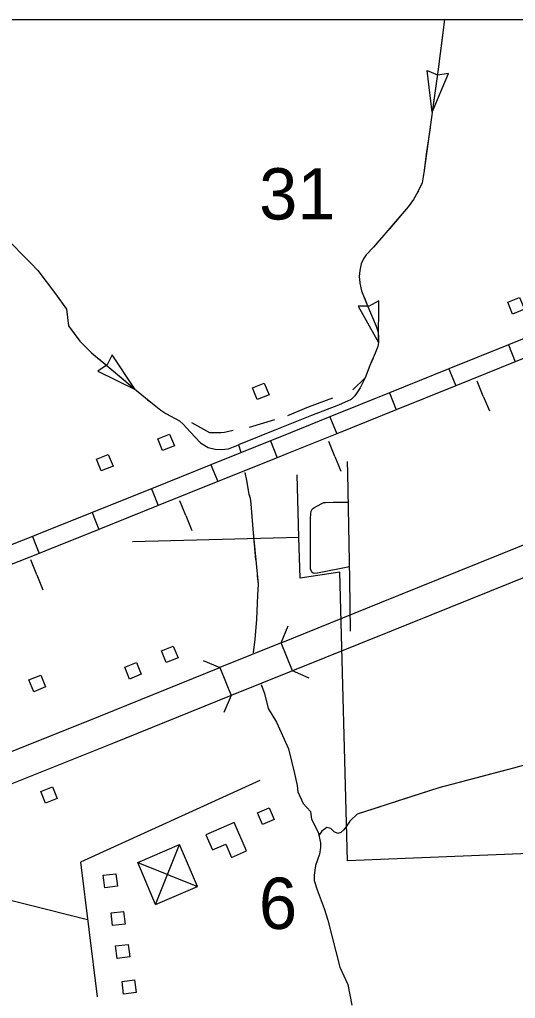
# Model space of a CAD drawing. Extents: x 155 to 3386, y 68 to 2138.
# Drawn here: x 1248.7 to 1365.4, y 1078.7 to 1309 of the extents above; entities that cross this region are included whole.
import ezdxf

# ---------------------------------------------------------------- set-up
doc = ezdxf.new("R2010")
doc.units = 0
for name, color, linetype in [('Default', 7, 'Continuous'), ('E_No Plot', 7, 'Continuous'), ('Level 15', 7, 'Continuous'), ('Level 32', 7, 'Continuous'), ('Level 33', 7, 'Continuous'), ('Level 35', 7, 'Continuous'), ('Level 37', 7, 'Continuous'), ('Level 4', 7, 'Continuous'), ('Level 40', 7, 'Continuous'), ('Level 43', 7, 'Continuous'), ('Level 5', 7, 'Continuous'), ('Level 56', 7, 'Continuous'), ('Level 57', 7, 'Continuous'), ('Level 58', 7, 'Continuous'), ('Level 6', 7, 'Continuous')]:
    doc.layers.add(name, color=color, linetype=linetype)

msp = doc.modelspace()

# ---------------------------------------------------------------- linework, layer by layer
at = {"layer": 'Default'}
msp.add_lwpolyline([(1150.5, 1308.99), (2342.15, 1308.99), (2342.15, 348.58), (1150.5, 348.58)], close=True, dxfattribs=at)
at = {"layer": 'E_No Plot'}
msp.add_lwpolyline([(1150.5, 1308.99), (2342.15, 1308.99), (2342.15, 348.58), (1150.5, 348.58)], close=True, dxfattribs=at)
msp.add_lwpolyline([(1150.5, 1308.99), (2342.15, 1308.99), (2342.15, 348.58), (1150.5, 348.58)], close=True, dxfattribs=at)
at = {"layer": 'Level 15'}
for p, q in [((1312.94, 1155.76), (1310.27, 1162.39)), ((1295.82, 1156.56), (1298.5, 1149.93))]:
    msp.add_line(p, q, dxfattribs=at)
for points in [[(1310.27, 1162.39), (1333.46, 1171.74), (1375.25, 1188.62)], [(1377.92, 1181.99), (1336.14, 1165.12), (1312.94, 1155.76)], [(1310.27, 1162.39), (1295.82, 1156.56)], [(1150.5, 1098.18), (1199.11, 1117.76), (1267.73, 1145.22), (1295.82, 1156.56)], [(1312.94, 1155.76), (1298.5, 1149.93)], [(1298.5, 1149.93), (1270.4, 1138.6), (1201.77, 1111.13), (1150.5, 1090.48)]]:
    msp.add_lwpolyline(points, dxfattribs=at)
at = {"layer": 'Level 32'}
for p, q in [((1363.72, 1232.44), (1365.33, 1228.47)), ((1349.73, 1226.8), (1351.33, 1222.83)), ((1335.74, 1221.16), (1337.34, 1217.19)), ((1321.75, 1215.52), (1323.35, 1211.54)), ((1307.76, 1209.88), (1309.36, 1205.91)), ((1293.76, 1204.25), (1295.36, 1200.28)), ((1279.77, 1198.62), (1281.36, 1194.65)), ((1265.77, 1193), (1267.37, 1189.02)), ((1251.78, 1187.38), (1253.35, 1183.39))]:
    msp.add_line(p, q, dxfattribs=at)
for points in [[(1377.71, 1238.08), (1363.72, 1232.44)], [(1363.72, 1232.44), (1349.73, 1226.8)], [(1379.32, 1234.11), (1365.33, 1228.47)], [(1365.33, 1228.47), (1351.33, 1222.83)], [(1349.73, 1226.8), (1335.74, 1221.16)], [(1335.74, 1221.16), (1321.75, 1215.52)], [(1351.33, 1222.83), (1337.34, 1217.19)], [(1337.34, 1217.19), (1323.35, 1211.54)], [(1321.75, 1215.52), (1309.99, 1210.78), (1307.76, 1209.88)], [(1323.35, 1211.54), (1311.59, 1206.8), (1309.36, 1205.91)], [(1307.76, 1209.88), (1293.76, 1204.25)], [(1309.36, 1205.91), (1295.36, 1200.28)], [(1293.76, 1204.25), (1279.77, 1198.62)], [(1295.36, 1200.28), (1281.36, 1194.65)], [(1279.77, 1198.62), (1265.77, 1193)], [(1265.77, 1193), (1253.07, 1187.89), (1251.78, 1187.38)], [(1281.36, 1194.65), (1267.37, 1189.02)], [(1267.37, 1189.02), (1254.65, 1183.91), (1253.35, 1183.39)], [(1251.78, 1187.38), (1237.75, 1181.86)], [(1253.35, 1183.39), (1239.31, 1177.87)]]:
    msp.add_lwpolyline(points, dxfattribs=at)
at = {"layer": 'Level 33'}
for points in [[(1326.58, 1165.11), (1326.41, 1177.23), (1326.08, 1194.02), (1325.99, 1202.26), (1325.88, 1205)], [(1326.35, 1180.22), (1318.84, 1178.74), (1318.19, 1178.68), (1317.82, 1178.74), (1317.47, 1178.98), (1317.29, 1179.37), (1317.21, 1179.79), (1317.16, 1180.77), (1317.16, 1191.62), (1317.23, 1192.69), (1317.34, 1193.3), (1317.58, 1193.78), (1317.97, 1194.15), (1318.82, 1194.63), (1319.84, 1195.13), (1320.3, 1195.35), (1320.71, 1195.41), (1322.48, 1195.48), (1326.07, 1195.48)]]:
    msp.add_lwpolyline(points, dxfattribs=at)
at = {"layer": 'Level 35'}
for points in [[(1305.58, 1152.54), (1306.37, 1150.4), (1307.2, 1146.9), (1309.15, 1143.68), (1310.99, 1139.71), (1311.96, 1137.4), (1312.72, 1134.51), (1313.4, 1131.61), (1314.02, 1128.83), (1314.16, 1127.31), (1315.46, 1124.57), (1317.16, 1122.69), (1317.38, 1120.85), (1318.95, 1117.8), (1319.56, 1115.31), (1319.49, 1114.19), (1319.27, 1112.64), (1318.37, 1110), (1318.01, 1107.69), (1318.05, 1106.46), (1318.73, 1104.26), (1320.39, 1099.89), (1321.22, 1097.11), (1324.04, 1086.02), (1325.95, 1082.01), (1326.89, 1077.13)], [(1328.23, 1122.1), (1326.41, 1120.37), (1325.67, 1119.25), (1325.05, 1118.39), (1324.31, 1117.71), (1323.63, 1117.53), (1322.71, 1117.9), (1321.97, 1118.7), (1321.04, 1118.88), (1319.81, 1118.08), (1319.13, 1117.05)]]:
    msp.add_lwpolyline(points, dxfattribs=at)
at = {"layer": 'Level 37'}
for points in [[(1310.27, 1162.39), (1311.95, 1166.33)], [(1291.88, 1158.23), (1295.82, 1156.56)], [(1316.89, 1154.08), (1312.94, 1155.76)], [(1298.5, 1149.93), (1296.82, 1145.99)]]:
    msp.add_lwpolyline(points, dxfattribs=at)
at = {"layer": 'Level 4'}
msp.add_lwpolyline([(1275.33, 1186.18), (1314.46, 1187.22)], dxfattribs=at)
at = {"layer": 'Level 40'}
for p, q in [((1357.83, 1220.43), (1356.41, 1223.92)), ((1357.83, 1220.43), (1359.25, 1216.94)), ((1322.89, 1206.23), (1321.47, 1209.72)), ((1322.89, 1206.23), (1324.31, 1202.74)), ((1287.85, 1192.29), (1286.46, 1195.79)), ((1287.85, 1192.29), (1289.24, 1188.78)), ((1252.8, 1178.36), (1251.39, 1181.85)), ((1252.8, 1178.36), (1254.21, 1174.86))]:
    msp.add_line(p, q, dxfattribs=at)
at = {"layer": 'Level 43'}
for p, q in [((1345.81, 1287.24), (1344.61, 1296.98)), ((1344.61, 1296.98), (1347.02, 1295.96)), ((1345.81, 1287.24), (1349.64, 1296.27)), ((1349.64, 1296.27), (1347.05, 1295.95)), ((1330.96, 1241.53), (1328.35, 1241.56)), ((1328.35, 1241.56), (1333.15, 1233.01)), ((1333.27, 1242.82), (1330.99, 1241.54)), ((1333.15, 1233.01), (1333.27, 1242.82)), ((1270.48, 1230.1), (1269.33, 1227.76)), ((1275.94, 1221.95), (1270.48, 1230.1)), ((1269.31, 1227.73), (1267.14, 1226.27)), ((1267.14, 1226.27), (1275.94, 1221.95))]:
    msp.add_line(p, q, dxfattribs=at)
for points in [[(1348.69, 1308.99), (1347.23, 1297.34), (1343.81, 1272.94), (1343.41, 1270.58), (1342.46, 1268.43), (1341.4, 1266.64), (1340.16, 1264.9), (1331.98, 1255.47), (1330.24, 1253.62), (1329.62, 1252.67), (1329.12, 1251.55), (1328.78, 1249.98), (1328.61, 1248.57), (1328.78, 1246.95), (1329.17, 1245.15), (1330.46, 1242.04), (1332.65, 1236.83), (1333.04, 1235.65), (1333.15, 1234.47), (1333.15, 1233.01), (1332.99, 1232.11), (1332.42, 1230.54), (1331.11, 1227.61), (1330.02, 1224.67), (1328.86, 1222.35), (1327.63, 1220.47), (1326.73, 1219.57), (1323.78, 1218.26), (1317.39, 1215.88), (1309.6, 1212.68), (1300.26, 1208.94)], [(1348.69, 1308.99), (1347.84, 1302.19)], [(1347.37, 1298.45), (1347.23, 1297.34), (1345.81, 1287.24)], [(1345.29, 1283.51), (1344.5, 1277.91)], [(1344.5, 1277.91), (1343.81, 1272.94), (1343.7, 1272.31)], [(1342.59, 1268.73), (1342.46, 1268.43), (1341.4, 1266.64), (1340.16, 1264.9), (1335.73, 1259.79)], [(1243.12, 1259.57), (1245.14, 1257.95), (1251.39, 1251.65), (1253.05, 1249.92), (1257.16, 1244.5), (1259.78, 1240.87), (1260.22, 1236.93), (1262.89, 1233.36), (1265.63, 1230.57), (1269.35, 1227.54), (1276.21, 1221.73), (1279.61, 1218.95), (1281.96, 1217.11), (1283.15, 1216.32), (1286.32, 1214.62), (1287.23, 1213.79), (1288.89, 1211.98), (1291.31, 1209.45), (1293.06, 1208.32), (1294.71, 1207.91), (1296.16, 1207.82), (1297.89, 1208.01), (1300.26, 1208.94), (1300.77, 1207.19)], [(1333.25, 1256.94), (1331.98, 1255.47), (1330.24, 1253.62), (1329.62, 1252.67), (1329.12, 1251.55), (1328.78, 1249.98), (1328.61, 1248.57), (1328.76, 1247.14)], [(1249.95, 1253.09), (1251.39, 1251.65), (1253.05, 1249.92), (1257.16, 1244.5), (1257.21, 1244.44)], [(1259.42, 1241.38), (1259.78, 1240.87), (1260.22, 1236.93), (1262.89, 1233.36), (1264.48, 1231.75)], [(1329.84, 1243.54), (1330.46, 1242.04), (1332.65, 1236.83), (1332.68, 1236.74)], [(1267.28, 1229.23), (1269.35, 1227.54), (1273.64, 1223.9)], [(1331.88, 1229.32), (1331.11, 1227.61), (1330.02, 1224.67), (1327.1, 1221.91)], [(1278.86, 1219.56), (1279.61, 1218.95), (1281.96, 1217.11), (1283.15, 1216.32), (1283.67, 1216.04)], [(1322.38, 1219.92), (1316.64, 1217.79), (1311.77, 1215.79)], [(1289.19, 1214.22), (1293.38, 1211.85), (1296.06, 1211.82), (1296.93, 1211.91), (1298.98, 1212.4)], [(1308.73, 1214.83), (1302.74, 1213.02)], [(1301.72, 1202.46), (1302.15, 1200.55), (1302.65, 1197.37), (1302.98, 1196.36), (1303.12, 1195.1), (1303.59, 1189.14), (1304.82, 1176.14), (1304.71, 1173.57), (1304.49, 1167.86), (1304.06, 1163.2), (1303.66, 1160.03)], [(1301.72, 1202.46), (1302.15, 1200.55), (1302.65, 1197.37), (1302.8, 1196.92)], [(1303.27, 1193.19), (1303.59, 1189.14), (1304.27, 1181.92)], [(1304.63, 1178.16), (1304.82, 1176.14), (1304.71, 1173.57), (1304.49, 1167.86), (1304.4, 1166.87)], [(1304.05, 1163.11), (1303.66, 1160.03)], [(1328.23, 1122.1), (1347.43, 1128.32), (1365.01, 1132.95), (1374.87, 1135.73)], [(1351.62, 1129.43), (1362.56, 1132.31)], [(1337.2, 1125.01), (1347.43, 1128.32), (1347.97, 1128.47)], [(1328.23, 1122.1), (1333.61, 1123.85)]]:
    msp.add_lwpolyline(points, dxfattribs=at)
at = {"layer": 'Level 56'}
for points in [[(1366.37, 1243.58), (1367.48, 1240.83), (1364.72, 1239.71), (1363.6, 1242.47)], [(1306.29, 1223.47), (1307.41, 1220.71), (1304.64, 1219.6), (1303.53, 1222.36)], [(1284.03, 1211.49), (1285.15, 1208.73), (1282.38, 1207.62), (1281.27, 1210.38)], [(1269.6, 1206.7), (1270.71, 1203.94), (1267.95, 1202.83), (1266.84, 1205.59)], [(1283.23, 1157.7), (1282.12, 1160.45), (1284.89, 1161.57), (1286, 1158.81)], [(1274.6, 1153.85), (1273.49, 1156.61), (1276.26, 1157.73), (1277.37, 1154.97)], [(1252.06, 1150.86), (1250.94, 1153.62), (1253.71, 1154.73), (1254.82, 1151.97)], [(1254.83, 1124.62), (1253.72, 1127.37), (1256.49, 1128.49), (1257.6, 1125.73)], [(1304.69, 1122.36), (1307.43, 1123.52), (1308.59, 1120.77), (1305.85, 1119.61)], [(1268.43, 1107.69), (1271.39, 1108.05), (1271.75, 1105.09), (1268.8, 1104.73)], [(1270.26, 1098.8), (1273.21, 1099.16), (1273.57, 1096.2), (1270.62, 1095.84)], [(1271.32, 1091.05), (1274.27, 1091.41), (1274.64, 1088.45), (1271.69, 1088.09)], [(1272.84, 1082.69), (1275.79, 1083.05), (1276.16, 1080.09), (1273.2, 1079.73)]]:
    msp.add_lwpolyline(points, close=True, dxfattribs=at)
for points in [[(1305.25, 1129.94), (1263.05, 1110.76), (1263.05, 1110.76)], [(1263.05, 1110.76), (1266.95, 1079.08)], [(1264.72, 1097.17), (1236.87, 1104.18)]]:
    msp.add_lwpolyline(points, dxfattribs=at)
at = {"layer": 'Level 57'}
for p, q in [((1276.52, 1110.68), (1286.38, 1114.89)), ((1280.74, 1100.83), (1286.38, 1114.89)), ((1290.59, 1105.04), (1286.38, 1114.89)), ((1280.74, 1100.83), (1276.52, 1110.68)), ((1276.52, 1110.68), (1290.59, 1105.04)), ((1280.74, 1100.83), (1290.59, 1105.04))]:
    msp.add_line(p, q, dxfattribs=at)
at = {"layer": 'Level 58'}
msp.add_lwpolyline([(1299.19, 1120.07), (1292.54, 1117.15), (1294.08, 1113.65), (1297.23, 1115.03), (1298.61, 1111.89), (1302.11, 1113.42)], close=True, dxfattribs=at)
at = {"layer": 'Level 6'}
msp.add_lwpolyline([(1388.19, 1039.98), (1386.09, 1113.47), (1325.89, 1111.06), (1324.11, 1178.97), (1314.71, 1177.54), (1314.46, 1187.22), (1314.07, 1201.9)], dxfattribs=at)

# ---------------------------------------------------------------- texts
at = {"layer": 'Level 5'}
for s, height, p in [('31', 12.069, (1305.09, 1261.96)), ('6', 12.07, (1305.04, 1095.05))]:
    msp.add_text(s, height=height, dxfattribs=at).set_placement(p)

doc.saveas('drawing.dxf')
